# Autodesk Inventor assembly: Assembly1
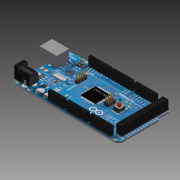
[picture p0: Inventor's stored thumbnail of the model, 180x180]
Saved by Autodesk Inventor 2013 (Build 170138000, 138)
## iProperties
Created: 2012-07
Part Number: Assembly1
Document SubType Name: Assembly
Designer: Paul
Author: Paul
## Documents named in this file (24)
- C:\Users\Paul\Documents\School\UROV\Arduino Mega\Assembly1.iam
- C:\Users\Paul\Documents\School\UROV\Arduino Mega\Part4.ipt
- C:\Users\Paul\Documents\School\UROV\Arduino Mega\Part6.ipt
- C:\Users\Paul\Documents\School\UROV\Arduino Mega\Part8.ipt
- C:\Users\Paul\Documents\School\UROV\Arduino Mega\Part10.ipt
- C:\Users\Paul\Documents\School\UROV\Arduino Mega\Part12.ipt
- C:\Users\Paul\Documents\School\UROV\Arduino Mega\Part14.ipt
- C:\Users\Paul\Documents\School\UROV\Arduino Mega\Part16.ipt
- C:\Users\Paul\Documents\School\UROV\Arduino Mega\Part18.ipt
- C:\Users\Paul\Documents\School\UROV\Arduino Mega\Part20.ipt
- C:\Users\Paul\Documents\School\UROV\Arduino Mega\Part22.ipt
- C:\Users\Paul\Documents\School\UROV\Arduino Mega\Part24.ipt
- C:\Users\Paul\Documents\School\UROV\Arduino Mega\Part26.ipt
- C:\Users\Paul\Documents\School\UROV\Arduino Mega\Part28.ipt
- C:\Users\Paul\Documents\School\UROV\Arduino Mega\Part30.ipt
- C:\Users\Paul\Documents\School\UROV\Arduino Mega\Part32.ipt
- C:\Users\Paul\Documents\School\UROV\Arduino Mega\Part34.ipt
- C:\Users\Paul\Documents\School\UROV\Arduino Mega\Part36.ipt
- C:\Users\Paul\Documents\School\UROV\Arduino Mega\Part38.ipt
- C:\Users\Paul\Documents\School\UROV\Arduino Mega\Part40.ipt
- C:\Users\Paul\Documents\School\UROV\Arduino Mega\Part42.ipt
- C:\Users\Paul\Documents\School\UROV\Arduino Mega\Part44.ipt
- C:\Users\Paul\Documents\School\UROV\Arduino Mega\Part46.ipt
- C:\Users\Paul\Documents\School\UROV\Arduino Mega\PCB-FIXED.ipt
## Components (23 placed, 23 different names)
1. Part4:1
2. Part6:1
3. Part8:1
4. Part10:1
5. Part12:1
6. Part14:1
7. Part16:1
8. Part18:1
9. Part20:1
10. Part22:1
11. Part24:1
12. Part26:1
13. Part28:1
14. Part30:1
15. Part32:1
16. Part34:1
17. Part36:1
18. Part38:1
19. Part40:1
20. Part42:1
21. Part44:1
22. Part46:1
23. PCB-FIXED:1
